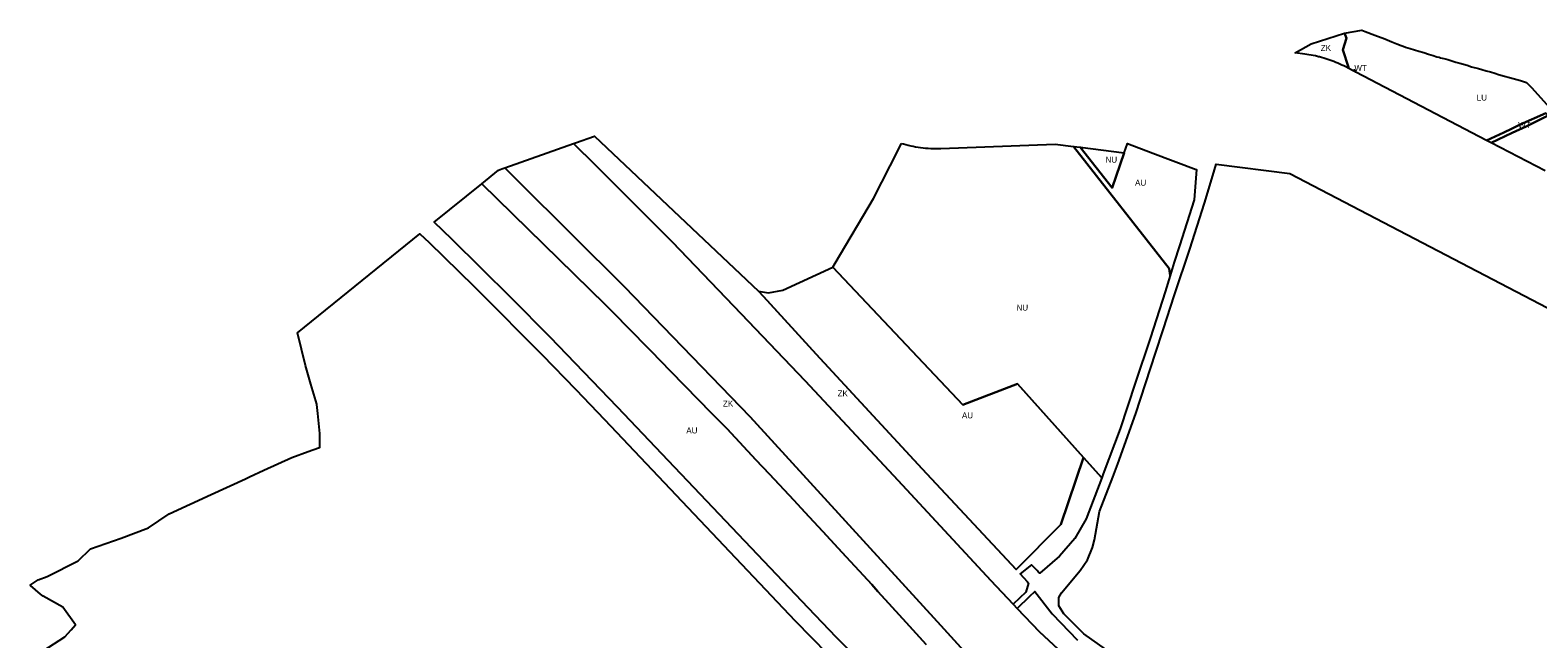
# Model space of a CAD drawing. Extents: x -545779 to -541342, y -1153413 to -1149956.
# Drawn here: x -543832 to -542580, y -1150461 to -1149956 of the extents above; entities that cross this region are included whole.
import ezdxf

# ---------------------------------------------------------------- set-up
doc = ezdxf.new("R2010")
doc.units = 0
for name, color, linetype in [('90640013', 7, 'Continuous'), ('90710013', 7, 'Continuous'), ('90730013', 7, 'Continuous'), ('90750013', 7, 'Continuous'), ('90770013', 7, 'Continuous')]:
    doc.layers.add(name, color=color, linetype=linetype)

msp = doc.modelspace()

# ---------------------------------------------------------------- linework, layer by layer
at = {"layer": '90640013'}
for points in [[(-542731.317, -1149990.631), (-542733.607, -1149989.436), (-542732.51, -1149988.72)], [(-542618.903, -1150049.266), (-542622.665, -1150047.304), (-542619.24, -1150045.68), (-542608.45, -1150040.68), (-542602.01, -1150037.74), (-542594.82, -1150034.12), (-542573.48, -1150024.63), (-542571.57, -1150026.72), (-542589.76, -1150035.73), (-542601.29, -1150041.03)]]:
    msp.add_lwpolyline(points, close=True, dxfattribs=at)
msp.add_lwpolyline([(-543056.63, -1150471.65), (-543076, -1150450.32), (-543155.13, -1150363.61), (-543234.26, -1150276.9), (-543338.6, -1150169.04), (-543426.68, -1150081.56), (-543438.05, -1150070.12), (-543381.13, -1150049.97), (-543362.85, -1150067.84), (-543298.72, -1150131.77), (-543241.68, -1150191.48), (-543188.54, -1150247.11), (-543111.5, -1150330.01), (-543034.47, -1150412.91), (-543015.84, -1150432.69), (-543015.26, -1150433.31), (-543013.1, -1150435.6), (-543012.54, -1150436.2), (-542994.14, -1150455.73), (-542959.14, -1150487.92)], dxfattribs=at)
at = {"layer": '90710013'}
for points in [[(-542763.135, -1149977.546), (-542763.203, -1149977.53), (-542764.885, -1149977.149), (-542766.641, -1149976.784), (-542768.401, -1149976.451), (-542770.166, -1149976.149), (-542771.933, -1149975.88), (-542773.702, -1149975.641), (-542781.773, -1149974.627), (-542781.773, -1149974.627), (-542768.46, -1149967.13), (-542740.73, -1149958.23), (-542738.92, -1149962.27), (-542742.17, -1149972.19), (-542737.34, -1149986.56), (-542736.94, -1149987.698), (-542739.654, -1149986.282), (-542741.244, -1149985.47), (-542742.85, -1149984.686), (-542744.472, -1149983.93), (-542746.109, -1149983.201), (-542747.76, -1149982.501), (-542749.425, -1149981.83), (-542751.102, -1149981.189), (-542752.792, -1149980.577), (-542754.492, -1149979.995), (-542756.203, -1149979.443), (-542757.924, -1149978.923), (-542759.653, -1149978.432), (-542761.39, -1149977.974), (-542762.35, -1149977.738)], [(-543091.46, -1150320.27), (-543013.48, -1150403.82), (-542976.41, -1150366.39), (-542957.48, -1150310.69), (-542942.32, -1150327.56), (-542955.27, -1150361.66), (-542964.77, -1150377.98), (-542977.28, -1150392.72), (-542993.725, -1150407.031), (-542994.75, -1150405.99), (-542996.07, -1150404.62), (-543000.66, -1150399.9), (-543010.11, -1150407.57), (-543004.38, -1150413.91), (-543003.17, -1150415.25), (-543005.33, -1150422.66), (-543015.84, -1150432.69), (-543034.47, -1150412.91), (-543111.5, -1150330.01), (-543188.54, -1150247.11), (-543241.68, -1150191.48), (-543298.72, -1150131.77), (-543362.85, -1150067.84), (-543381.13, -1150049.97), (-543379.5, -1150049.39), (-543363.67, -1150043.79), (-543227.35, -1150172.67), (-543223.32, -1150177.07), (-543179.45, -1150224.97)]]:
    msp.add_lwpolyline(points, close=True, dxfattribs=at)
for points in [[(-543088.15, -1150466.06), (-543104.73, -1150447.88), (-543116.27, -1150435.21), (-543128.31, -1150422.01), (-543133.39, -1150416.44), (-543140.32, -1150408.83), (-543154.52, -1150393.26), (-543161.14, -1150386), (-543173.94, -1150372.26), (-543185.37, -1150360.02), (-543191.92, -1150353), (-543198.13, -1150346.36), (-543218.3, -1150324.76), (-543229.52, -1150312.74), (-543253.54, -1150287.02), (-543260.72, -1150279.68), (-543266.66, -1150273.62), (-543277.26, -1150262.79), (-543288.76, -1150251.03), (-543300.47, -1150239.08), (-543316.62, -1150222.57), (-543322.63, -1150216.43), (-543330.72, -1150208.16), (-543351.82, -1150186.6), (-543354.66, -1150183.76), (-543457.287, -1150083.301), (-543443.298, -1150071.977), (-543440.48, -1150070.98), (-543438.05, -1150070.12), (-543426.68, -1150081.56), (-543338.6, -1150169.04), (-543234.26, -1150276.9), (-543155.13, -1150363.61), (-543076, -1150450.32), (-543056.63, -1150471.65)], [(-542959.14, -1150487.92), (-542994.14, -1150455.73), (-543012.54, -1150436.2), (-543002, -1150426.12), (-542997.835, -1150422.106), (-542983.39, -1150440.67), (-542962.35, -1150462.51)]]:
    msp.add_lwpolyline(points, dxfattribs=at)
at = {"layer": '90730013'}
for points in [[(-543108.581, -1150049.834), (-543107.077, -1150050.273), (-543105.058, -1150050.817), (-543103.027, -1150051.319), (-543100.985, -1150051.779), (-543098.933, -1150052.197), (-543096.872, -1150052.573), (-543094.803, -1150052.905), (-543092.729, -1150053.194), (-543090.65, -1150053.44), (-543088.568, -1150053.643), (-543086.484, -1150053.802), (-543084.399, -1150053.918), (-543082.315, -1150053.99), (-543080.232, -1150054.02), (-543078.154, -1150054.006), (-543076.08, -1150053.95), (-542980.889, -1150050.388), (-542965.771, -1150052.289), (-542886.29, -1150153.77), (-542885.42, -1150159.63), (-542889.52, -1150173.07), (-542901.69, -1150211.18), (-542914.41, -1150249.01), (-542927.06, -1150286.9), (-542941.11, -1150324.36), (-542942.32, -1150327.56), (-542957.48, -1150310.69), (-543012.33, -1150249.67), (-543057.62, -1150266.96), (-543165.76, -1150152.71), (-543163.67, -1150149.18), (-543131.93, -1150095.64), (-543118.02, -1150068.52)], [(-542960.131, -1150052.997), (-542923.667, -1150057.58), (-542933.64, -1150086.82)]]:
    msp.add_lwpolyline(points, close=True, dxfattribs=at)
at = {"layer": '90750013'}
for points in [[(-542965.771, -1150052.289), (-542960.131, -1150052.997), (-542933.64, -1150086.82), (-542923.667, -1150057.58), (-542921.04, -1150049.88), (-542900, -1150057.8), (-542900, -1150057.8), (-542863.843, -1150071.412), (-542863.693, -1150071.469), (-542863.6, -1150071.503), (-542863.6, -1150071.503), (-542863.53, -1150071.53), (-542865.66, -1150096.71), (-542877.83, -1150134.82), (-542882.02, -1150148.51), (-542885.42, -1150159.63), (-542886.29, -1150153.77)], [(-543179.45, -1150224.97), (-543223.32, -1150177.07), (-543227.35, -1150172.67), (-543219.01, -1150174.06), (-543207.09, -1150171.73), (-543165.76, -1150152.71), (-543057.62, -1150266.96), (-543012.33, -1150249.67), (-542957.48, -1150310.69), (-542976.41, -1150366.39), (-543013.48, -1150403.82), (-543091.46, -1150320.27)]]:
    msp.add_lwpolyline(points, close=True, dxfattribs=at)
for points in [[(-542939.27, -1150470.05), (-542957.08, -1150457.18), (-542973.67, -1150440.8), (-542978.05, -1150433.99), (-542977.98, -1150431.6), (-542977.86, -1150427.24), (-542975.75, -1150423.15), (-542960.11, -1150404.77), (-542954.03, -1150395.7), (-542949.96, -1150385.51), (-542948.44, -1150379.28), (-542944.25, -1150355.53), (-542933.12, -1150327.25), (-542928.95, -1150316.13), (-542914.11, -1150274.31), (-542897.56, -1150224), (-542891.21, -1150204.63), (-542881.9, -1150175.5), (-542869.26, -1150137.55), (-542857.09, -1150099.45), (-542850.102, -1150076.585), (-542847.23, -1150067.187), (-542786.029, -1150074.879), (-542377.782, -1150287.823)], [(-543132.527, -1150490.655), (-543162.992, -1150460.034), (-543186.011, -1150436.046), (-543344.484, -1150268.967), (-543372.384, -1150239.793), (-543400.503, -1150210.87), (-543432.945, -1150178.086), (-543457.476, -1150153.701), (-543482.186, -1150129.482), (-543496.832, -1150115.312), (-543457.287, -1150083.301), (-543354.66, -1150183.76), (-543351.82, -1150186.6), (-543330.72, -1150208.16), (-543322.63, -1150216.43), (-543316.62, -1150222.57), (-543300.47, -1150239.08), (-543288.76, -1150251.03), (-543277.26, -1150262.79), (-543266.66, -1150273.62), (-543260.72, -1150279.68), (-543253.54, -1150287.02), (-543229.52, -1150312.74), (-543218.3, -1150324.76), (-543198.13, -1150346.36), (-543191.92, -1150353), (-543185.37, -1150360.02), (-543173.94, -1150372.26), (-543161.14, -1150386), (-543154.52, -1150393.26), (-543140.32, -1150408.83), (-543133.39, -1150416.44), (-543128.31, -1150422.01), (-543116.27, -1150435.21), (-543104.73, -1150447.88), (-543088.15, -1150466.06)], [(-543821.65, -1150471.39), (-543803.6, -1150459.91), (-543798.35, -1150453.88), (-543794.72, -1150449.7), (-543805.24, -1150435.1), (-543821.63, -1150425.96), (-543823.65, -1150424.26), (-543832.16, -1150417.11), (-543832.38, -1150416.93), (-543825.83, -1150412.53), (-543818.18, -1150409.77), (-543792.47, -1150396.57), (-543782.14, -1150386.64), (-543756.74, -1150377.92), (-543734.1, -1150369.12), (-543716.97, -1150357.6), (-543682.13, -1150341.56), (-543653.5, -1150328.38), (-543650.2, -1150326.86), (-543638.38, -1150321.45), (-543614.97, -1150310.74), (-543601.55, -1150305.9), (-543592.79, -1150302.75), (-543591.79, -1150302.39), (-543591.7, -1150290.93), (-543593.39, -1150274.14), (-543594.13, -1150266.72), (-543594.19, -1150266.51), (-543599.11, -1150249.93), (-543603.71, -1150234.39), (-543610.301, -1150207.162), (-543508.577, -1150124.819), (-543500.913, -1150132.207), (-543463.914, -1150168.427), (-543443.557, -1150188.687), (-543423.305, -1150209.081), (-543407.21, -1150225.461), (-543379.192, -1150254.349), (-543355.349, -1150279.309), (-543196.816, -1150446.451), (-543143.124, -1150501.272)]]:
    msp.add_lwpolyline(points, dxfattribs=at)
at = {"layer": '90770013'}
for points in [[(-542573.48, -1150024.63), (-542594.82, -1150034.12), (-542602.01, -1150037.74), (-542608.45, -1150040.68), (-542619.24, -1150045.68), (-542622.665, -1150047.304), (-542731.317, -1149990.631), (-542732.51, -1149988.72), (-542733.607, -1149989.436), (-542736.94, -1149987.698), (-542737.34, -1149986.56), (-542742.17, -1149972.19), (-542738.92, -1149962.27), (-542740.73, -1149958.23), (-542726.36, -1149955.69), (-542723.57, -1149956.76), (-542715.56, -1149959.94), (-542707.31, -1149963.03), (-542701.31, -1149965.4), (-542697.28, -1149966.93), (-542693.64, -1149968.41), (-542692.03, -1149969.06), (-542689.99, -1149969.76), (-542686.19, -1149970.84), (-542682.53, -1149971.95), (-542678.83, -1149973.15), (-542674.85, -1149974.34), (-542670.79, -1149975.65), (-542667.12, -1149976.75), (-542663.96, -1149977.75), (-542662.04, -1149978.25), (-542660.93, -1149978.57), (-542658.24, -1149979.32), (-542654.96, -1149980.15), (-542651.47, -1149981.27), (-542648.08, -1149982.3), (-542644.76, -1149983.2), (-542641.79, -1149984.09), (-542638.83, -1149984.89), (-542635.05, -1149986.05), (-542629.39, -1149987.63), (-542626.57, -1149988.45), (-542623.04, -1149989.49), (-542619.36, -1149990.47), (-542615.93, -1149991.44), (-542612.73, -1149992.41), (-542607.66, -1149993.89), (-542603.49, -1149995.02), (-542594.54, -1149997.6), (-542591.2, -1149998.56), (-542589.39, -1149999.09), (-542585.14, -1150003.72), (-542567.91, -1150022.74)], [(-542573.976, -1150072.7), (-542618.903, -1150049.266), (-542601.29, -1150041.03), (-542589.76, -1150035.73), (-542571.57, -1150026.72)]]:
    msp.add_lwpolyline(points, dxfattribs=at)

# ---------------------------------------------------------------- texts
at = {"layer": '90640013'}
for p in [(-542732.478, -1149989.596), (-542596.423, -1150036.948)]:
    msp.add_text('WT', height=5, rotation=0, dxfattribs=at).set_placement(p)
at = {"layer": '90710013'}
for p in [(-542760.365, -1149972.964), (-543256.958, -1150268.481), (-543161.725, -1150260.066)]:
    msp.add_text('ZK', height=5, rotation=360, dxfattribs=at).set_placement(p)
at = {"layer": '90730013'}
for p in [(-542939.146, -1150065.799), (-543013.104, -1150188.697)]:
    msp.add_text('NU', height=5, rotation=360, dxfattribs=at).set_placement(p)
at = {"layer": '90750013'}
for rotation, p in [(360, (-542914.65, -1150084.922)), (0, (-543058.435, -1150278.265)), (0, (-543287.386, -1150290.8))]:
    msp.add_text('AU', height=5, rotation=rotation, dxfattribs=at).set_placement(p)
at = {"layer": '90770013'}
msp.add_text('LU', height=5, rotation=360, dxfattribs=at).set_placement((-542630.896, -1150014.195))

doc.saveas('drawing.dxf')
